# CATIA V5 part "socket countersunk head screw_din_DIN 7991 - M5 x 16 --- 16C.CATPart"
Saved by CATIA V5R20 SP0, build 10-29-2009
Part number: socket countersunk head screw_din_DIN 7991 - M5 x 16 --- 16C
Revision: ANY
Definition: UNKNOWN
Nomenclature: socket countersunk head screw_din_DIN 7991 - M5 x 16 --- 16C
Source: Unknown
Bounding box of the stored display mesh (mm): x 0 to 16, y -4.82 to 4.82, z -4.82 to 4.82
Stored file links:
  C:\Users\Utente\Desktop\IO LAVORO\3D X SITO CF\CUMSA\3D files GR\GR 182622-10\socket countersunk head screw_din_DIN 7991 - M5 x 16 --- 16C.CATPart
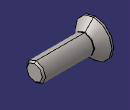
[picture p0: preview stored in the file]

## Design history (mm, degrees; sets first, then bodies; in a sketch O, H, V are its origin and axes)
Body1 "Hex" (main body)
  Solid1: solid without history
